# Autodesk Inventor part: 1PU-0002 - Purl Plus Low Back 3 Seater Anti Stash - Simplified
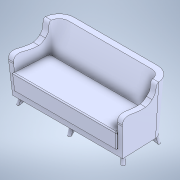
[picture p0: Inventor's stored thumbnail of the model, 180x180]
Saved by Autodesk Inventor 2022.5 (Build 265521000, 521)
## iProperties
Created: 2025-09
Part Number: 1PU-0002 - Purl Plus Low Back 3 Seater Anti Stash - Simplified
Material: Generic
Document SubType Name: Modeling
Designer: Mark.Glazzard
Density: 1 g/cm^3
Appearance: Default
Author: Mark.Glazzard
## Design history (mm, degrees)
derived "1PU-0002 - Purl Plus Low Back 3 Seater Anti Stash - Simplifi"
body "Solid1"
node "1PU-0002 - BEECH FEET.ipt:1"
node "1PU-0002 - BEECH FEET.ipt:2"
body "Solid2"
node "1PU-0002 - BEECH FEET.ipt:3"
body "Solid3"
node "1PU-0002 - BEECH FEET.ipt:4"
body "Solid4"
node "1PU-0002 - FR BLACK LINING FABRIC - 2SEATER.ipt:1"
body "Solid5"
node "1PU-0002 - Upholstery 2.ipt:1"
body "Solid6"
node "1PU-0002 - Upholstery 1.ipt:1"
body "Solid7"
node "1PU-0002 - BEECH FEET.ipt:5"
body "Solid8"
node "1PU-0002 - BEECH FEET.ipt:6"
body "Solid9"
